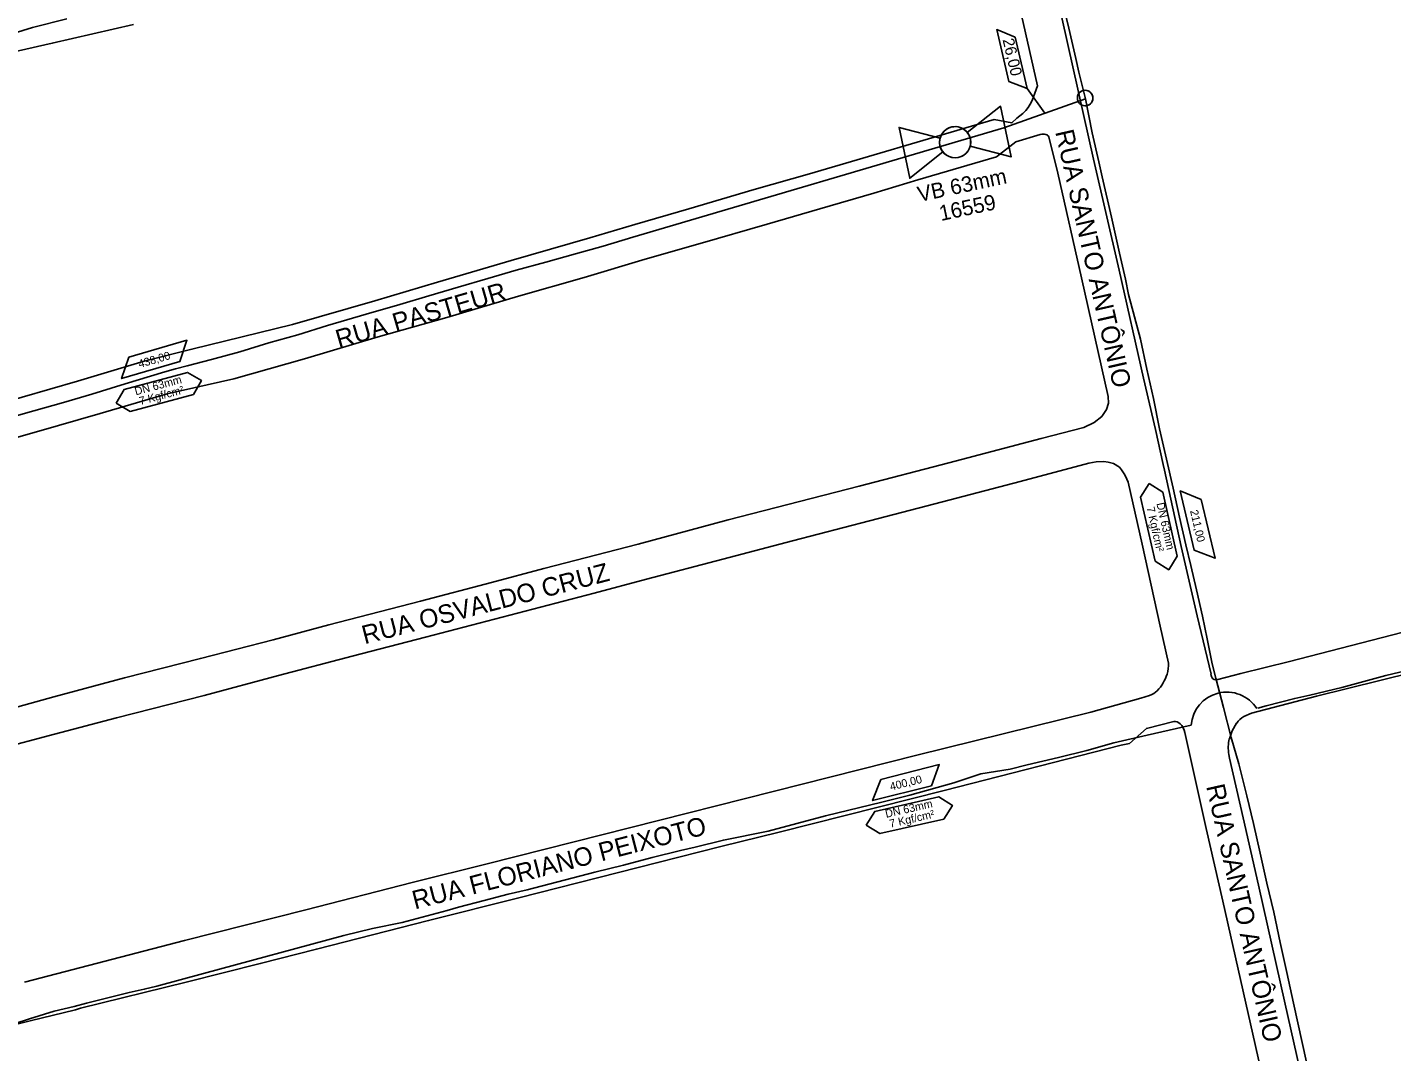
# Model space of a CAD drawing. Extents: x 656692 to 673945, y 7585994 to 7599066.
# Drawn here: x 669316 to 669847, y 7594394 to 7594792 of the extents above; entities that cross this region are included whole.
import ezdxf

# ---------------------------------------------------------------- set-up
doc = ezdxf.new("R2010")
doc.units = 0
for name, color, linetype in [('LEADER', 7, 'Continuous'), ('LOGRADOURO', 7, 'Continuous'), ('LOGRADOURO_TEXTO', 7, 'Continuous'), ('MEIO FIO', 7, 'Continuous'), ('SIMBOLO', 7, 'Continuous'), ('TEXTO', 7, 'Continuous'), ('TUBO_PEAD_GN_63', 7, 'Continuous'), ('VALVULA_PEAD_63', 7, 'Continuous')]:
    doc.layers.add(name, color=color, linetype=linetype)

# ---------------------------------------------------------------- blocks, each defined once
blk = doc.blocks.new('INTERLIGACAO_9')
at = {"layer": 'SIMBOLO'}
blk.add_circle((0, 0), 4.19, dxfattribs=at)
for start, end in [(0, 180), (180, 0)]:
    blk.add_arc((0, 0), 4.19, start, end, dxfattribs=at)
blk = doc.blocks.new('VALVULA_PEAD_DN_16')
at = {"layer": 'VALVULA_PEAD_63'}
for points in [[(-0.0374, 0.0187), (-0.1395, 0.0698), (-0.1395, -0.0698), (-0.0374, -0.0187)], [(-0.0374, -0.0187), (-0.1395, -0.0698), (-0.1395, 0.0698), (-0.0374, 0.0187)], [(0.0374, -0.0187), (0.1395, -0.0698), (0.1395, 0.0698), (0.0374, 0.0187)], [(0.0374, -0.0187), (0.1395, -0.0698), (0.1395, 0.0698), (0.0374, 0.0187)]]:
    blk.add_lwpolyline(points, dxfattribs=at)
blk.add_circle((0, 0), 0.0419, dxfattribs=at)
for start, end in [(90, 270), (270, 90), (153.4349, 206.5651), (333.4349, 26.5651)]:
    blk.add_arc((0, 0), 0.0419, start, end, dxfattribs=at)

msp = doc.modelspace()

# ---------------------------------------------------------------- linework, layer by layer
at = {"layer": 'LEADER'}
msp.add_line((669705.15, 7594768.25), (669711.96, 7594758.65), dxfattribs=at)
at = {"layer": 'LOGRADOURO'}
for points in [[(669708.04, 7594766.52), (669709.08, 7594769.39), (669698.21, 7594817.63)], [(669357.4, 7594793.19), (669325.77, 7594785.92), (669299.44, 7594779.98), (669291.66, 7594778.21), (669288.9, 7594777.62), (669281.2, 7594775.94), (669248.67, 7594768.12), (669226.84, 7594761.44), (669204.91, 7594756.34), (669201.88, 7594754.21), (669198.59, 7594751.08), (669196.54, 7594747.55), (669195.4, 7594743.11), (669195.58, 7594737.81), (669202.58, 7594710.45), (669204.55, 7594702.59), (669213.03, 7594669.59), (669218.51, 7594648.19), (669222.91, 7594633.24), (669224.67, 7594630.86), (669228.67, 7594628.02), (669233.37, 7594626.44), (669237.53, 7594626.34)], [(669237.1, 7594626.35), (669237.53, 7594626.34), (669243.7, 7594627.82), (669256.03, 7594631.66), (669281.62, 7594638.85), (669335.66, 7594654.49), (669361.52, 7594662.29), (669380.11, 7594666.85), (669419.27, 7594676.5), (669451.28, 7594685.7), (669475.65, 7594692.9), (669504.32, 7594701.36), (669535, 7594710.23), (669552.51, 7594715.34), (669573.47, 7594721.5), (669598.86, 7594729.05), (669620.42, 7594735.05), (669641.21, 7594741.19), (669692.23, 7594756.22), (669699.16, 7594754.93), (669701.07, 7594756.72)], [(669710.23, 7594750.4), (669700.67, 7594747.62), (669693.24, 7594741.71), (669662.53, 7594732.82), (669645.51, 7594727.58), (669624.46, 7594721.46), (669603.9, 7594715.53), (669577.86, 7594708.04), (669556.46, 7594701.88), (669532.76, 7594694.82), (669507.17, 7594687.54), (669479.33, 7594679.26), (669452.63, 7594671.71), (669423.99, 7594663.08), (669396.46, 7594655.38), (669370.52, 7594649.55), (669344.42, 7594641.91), (669319.65, 7594634.78), (669289.4, 7594626.23), (669263.46, 7594618.92)], [(669716.75, 7594736.58), (669717.02, 7594735.41), (669713.54, 7594749.5)], [(669717.02, 7594735.41), (669726.21, 7594694.71), (669736.62, 7594648.53), (669736.77, 7594645.94), (669736.02, 7594643.39), (669734.15, 7594640.73), (669731.23, 7594638.36), (669727.21, 7594636.49), (669710.61, 7594632.21), (669674.58, 7594622.69), (669639.78, 7594613.65), (669588.78, 7594600.48), (669553.81, 7594591.1), (669517.03, 7594581.51), (669496.65, 7594576.18), (669469.07, 7594568.91), (669433.42, 7594559.71), (669411.7, 7594553.81), (669383.46, 7594546.62), (669353.86, 7594539.03), (669326.39, 7594531.68), (669299.71, 7594524.3)], [(669789.44, 7594524.01), (669792.46, 7594525.26), (669817.72, 7594531.85), (669854.93, 7594541.17)], [(669317.17, 7594405.59), (669334.78, 7594409.84), (669336.84, 7594410.54), (669377.87, 7594420.65), (669406.73, 7594427.88), (669428.57, 7594433.54), (669472.21, 7594444.57), (669507.35, 7594453.49), (669561.45, 7594467.14), (669585.87, 7594473.39), (669608.65, 7594479.02), (669672.81, 7594495.25), (669741.75, 7594512.81), (669744.93, 7594513.55), (669751.5, 7594519.38), (669762.15, 7594522.05)], [(669766.41, 7594517.77), (669772.45, 7594490.95), (669774.82, 7594480.45), (669781.23, 7594452.2), (669791.14, 7594408.52), (669796.84, 7594383.21)], [(669783.78, 7594515.34), (669784.86, 7594518.45), (669786.63, 7594521.44)], [(670024.2, 7594248.68), (669972.2, 7594236.37), (669931.63, 7594226.92), (669869.93, 7594210.34), (669856.39, 7594207.15), (669854.57, 7594207.25), (669852.09, 7594209.19), (669851.15, 7594212.12), (669848.91, 7594221.72), (669841.45, 7594254.98), (669835.32, 7594280.76), (669830.05, 7594304.69), (669825.15, 7594326.15), (669817.99, 7594357.4), (669812.29, 7594382.1), (669805.54, 7594412.15), (669795.17, 7594458.34), (669789.2, 7594484.52), (669783.85, 7594507.78), (669783.6, 7594509.19)], [(669317.17, 7594405.59), (669298.03, 7594400.79), (669290.46, 7594398.86), (669287.17, 7594397.24), (669285.24, 7594393.34), (669285.69, 7594389.46), (669291.47, 7594367.59), (669298.18, 7594341.51), (669310.16, 7594295.23), (669315.1, 7594276.26), (669319.11, 7594267.04), (669323.78, 7594264.11), (669327.81, 7594262.48), (669331.42, 7594262.39), (669350.64, 7594266.44)]]:
    msp.add_lwpolyline(points, dxfattribs=at)
for centre, radius, start, end in [((669692.28, 7594770.35), 16.22, 302.7974, 346.333), ((669711.46, 7594745.18), 5.36, 79.6086, 103.2517), ((669711.99, 7594748.81), 1.7, 24.0037, 75.1752), ((669793.34, 7594516.94), 8.07, 118.8277, 146.1888), ((669762.33, 7594518.35), 3.71, 50.2693, 92.8497), ((669759.22, 7594516.32), 7.34, 11.4245, 41.6393), ((669798.13, 7594511.86), 14.77, 166.3521, 190.3999)]:
    msp.add_arc(centre, radius, start, end, dxfattribs=at)
at = {"layer": 'MEIO FIO'}
for p, q in [((669730.96, 7594740.8), (669716.35, 7594806.03)), ((669740.87, 7594697.65), (669730.96, 7594740.8)), ((669730.96, 7594740.8), (669730.96, 7594740.8)), ((669750.33, 7594655.62), (669740.87, 7594697.65)), ((669740.87, 7594697.65), (669740.87, 7594697.65)), ((669755.03, 7594635.61), (669750.33, 7594655.62)), ((669750.33, 7594655.62), (669750.33, 7594655.62)), ((669758.02, 7594622), (669755.03, 7594635.61)), ((669755.03, 7594635.61), (669755.03, 7594635.61)), ((669729.16, 7594622.59), (669702.34, 7594615.4)), ((669732.01, 7594623.08), (669729.16, 7594622.59)), ((669729.16, 7594622.59), (669729.16, 7594622.59)), ((669734.92, 7594623.14), (669732.01, 7594623.08)), ((669732.01, 7594623.08), (669732.01, 7594623.08)), ((669736.61, 7594622.99), (669734.92, 7594623.14)), ((669734.92, 7594623.14), (669734.92, 7594623.14)), ((669738.67, 7594622.45), (669736.61, 7594622.99)), ((669736.61, 7594622.99), (669736.61, 7594622.99)), ((669741.04, 7594620.94), (669738.67, 7594622.45)), ((669738.67, 7594622.45), (669738.67, 7594622.45)), ((669741.87, 7594619.94), (669741.04, 7594620.94)), ((669741.04, 7594620.94), (669741.04, 7594620.94)), ((669742.92, 7594618.4), (669741.87, 7594619.94)), ((669741.87, 7594619.94), (669741.87, 7594619.94)), ((669758.52, 7594619.77), (669758.02, 7594622)), ((669758.02, 7594622), (669758.02, 7594622)), ((669765.09, 7594590.11), (669758.52, 7594619.77)), ((669758.52, 7594619.77), (669758.52, 7594619.77)), ((669702.34, 7594615.4), (669672.24, 7594607.5)), ((669702.34, 7594615.4), (669702.34, 7594615.4)), ((669743.43, 7594617.51), (669742.92, 7594618.4)), ((669742.92, 7594618.4), (669742.92, 7594618.4)), ((669744.38, 7594615.11), (669743.43, 7594617.51)), ((669743.43, 7594617.51), (669743.43, 7594617.51)), ((669749.88, 7594591.01), (669744.38, 7594615.11)), ((669744.38, 7594615.11), (669744.38, 7594615.11)), ((669672.24, 7594607.5), (669643.71, 7594600.12)), ((669672.24, 7594607.5), (669672.24, 7594607.5)), ((669643.71, 7594600.12), (669613.86, 7594592.31)), ((669643.71, 7594600.12), (669643.71, 7594600.12)), ((669613.86, 7594592.31), (669586.69, 7594585.25)), ((669613.86, 7594592.31), (669613.86, 7594592.31)), ((669756.9, 7594559.18), (669749.88, 7594591.01)), ((669749.88, 7594591.01), (669749.88, 7594591.01)), ((669771.26, 7594563.21), (669765.09, 7594590.11)), ((669765.09, 7594590.11), (669765.09, 7594590.11)), ((669586.69, 7594585.25), (669556.98, 7594577.39)), ((669586.69, 7594585.25), (669586.69, 7594585.25)), ((669556.98, 7594577.39), (669536.6, 7594572.02)), ((669556.98, 7594577.39), (669556.98, 7594577.39)), ((669536.6, 7594572.02), (669500.8, 7594562.7)), ((669536.6, 7594572.02), (669536.6, 7594572.02)), ((669500.8, 7594562.7), (669471.07, 7594554.92)), ((669500.8, 7594562.7), (669500.8, 7594562.7)), ((669776.65, 7594540.51), (669771.26, 7594563.21)), ((669771.26, 7594563.21), (669771.26, 7594563.21)), ((669471.07, 7594554.92), (669442.49, 7594547.52)), ((669471.07, 7594554.92), (669471.07, 7594554.92)), ((669760.12, 7594544.79), (669756.9, 7594559.18)), ((669756.9, 7594559.18), (669756.9, 7594559.18)), ((669854.97, 7594557.66), (669807.25, 7594545.44)), ((669442.49, 7594547.52), (669413.86, 7594539.9)), ((669442.49, 7594547.52), (669442.49, 7594547.52)), ((669760.12, 7594544.79), (669760.12, 7594544.79)), ((669807.25, 7594545.44), (669788.25, 7594540.66)), ((669807.25, 7594545.44), (669807.25, 7594545.44)), ((669413.86, 7594539.9), (669384.92, 7594532.12)), ((669413.86, 7594539.9), (669413.86, 7594539.9)), ((669759.53, 7594540.49), (669759.53, 7594540.49)), ((669776.65, 7594540.51), (669776.65, 7594540.51)), ((669788.25, 7594540.66), (669779.34, 7594538.42)), ((669788.25, 7594540.66), (669788.25, 7594540.66)), ((669755.76, 7594534.01), (669755.76, 7594534.01)), ((669779.34, 7594538.42), (669779.34, 7594538.42)), ((669384.92, 7594532.12), (669350.83, 7594523.45)), ((669384.92, 7594532.12), (669384.92, 7594532.12)), ((669729.9, 7594525.7), (669749.34, 7594531.17)), ((669749.34, 7594531.17), (669752.78, 7594532.2)), ((669749.34, 7594531.17), (669749.34, 7594531.17)), ((669752.78, 7594532.2), (669752.78, 7594532.2)), ((669350.83, 7594523.45), (669326.62, 7594517.09)), ((669350.83, 7594523.45), (669350.83, 7594523.45)), ((669662.16, 7594508.99), (669729.9, 7594525.7)), ((669729.9, 7594525.7), (669729.9, 7594525.7)), ((669326.62, 7594517.09), (669299.28, 7594509.87)), ((669326.62, 7594517.09), (669326.62, 7594517.09)), ((669495.07, 7594466.67), (669662.16, 7594508.99)), ((669662.16, 7594508.99), (669662.16, 7594508.99)), ((669465.88, 7594459.48), (669495.07, 7594466.67)), ((669495.07, 7594466.67), (669495.07, 7594466.67)), ((669424.45, 7594448.75), (669465.88, 7594459.48)), ((669465.88, 7594459.48), (669465.88, 7594459.48)), ((669377.26, 7594436.84), (669424.45, 7594448.75)), ((669424.45, 7594448.75), (669424.45, 7594448.75)), ((669314.98, 7594420.66), (669377.26, 7594436.84)), ((669377.26, 7594436.84), (669377.26, 7594436.84))]:
    msp.add_line(p, q, dxfattribs=at)
for centre, radius, start, end in [((669745.85, 7594544.55), 14.27, 343.5106, 0.9964), ((669744.23, 7594545.06), 15.97, 316.2326, 343.4025), ((669778.63, 7594540.29), 2, 173.6588, 290.846), ((669748.73, 7594542.24), 10.82, 291.9604, 310.5304)]:
    msp.add_arc(centre, radius, start, end, dxfattribs=at)
at = {"layer": 'SIMBOLO'}
for points in [[(669350.63, 7594645.84), (669353.77, 7594651.26), (669378.44, 7594657.83), (669383.86, 7594654.7), (669380.72, 7594649.28), (669356.05, 7594642.71), (669350.63, 7594645.84)], [(669752.6, 7594614.65), (669757.9, 7594611.31), (669763.54, 7594586.41), (669760.21, 7594581.11), (669754.91, 7594584.45), (669749.27, 7594609.35), (669752.6, 7594614.65)], [(669642.5, 7594481.75), (669645.82, 7594487.05), (669670.71, 7594492.75), (669676.02, 7594489.42), (669672.69, 7594484.12), (669647.8, 7594478.42), (669642.5, 7594481.75)]]:
    msp.add_lwpolyline(points, dxfattribs=at)
at = {"layer": 'TEXTO'}
for points in [[(669700.44, 7594788.3), (669705.15, 7594768.25), (669697.99, 7594771.02), (669693.26, 7594791.2), (669700.44, 7594788.3)], [(669355.62, 7594663.83), (669378.2, 7594670.37), (669375.46, 7594662.04), (669352.74, 7594655.46), (669355.62, 7594663.83)], [(669772.86, 7594608.43), (669778.23, 7594585.55), (669770.06, 7594588.71), (669764.66, 7594611.74), (669772.86, 7594608.43)], [(669772.86, 7594608.43), (669778.23, 7594585.55), (669770.06, 7594588.71), (669764.66, 7594611.73), (669772.86, 7594608.43)], [(669648.12, 7594499.54), (669670.91, 7594505.28), (669667.88, 7594497.06), (669644.95, 7594491.29), (669648.12, 7594499.54)], [(669648.12, 7594499.54), (669670.91, 7594505.28), (669667.88, 7594497.06), (669644.95, 7594491.29), (669648.12, 7594499.54)]]:
    msp.add_lwpolyline(points, dxfattribs=at)
at = {"layer": 'TUBO_PEAD_GN_63'}
for points in [[(669196.25, 7594762.02), (669207.32, 7594764.89), (669217.32, 7594766.63), (669226.36, 7594768.54), (669242.04, 7594772.38), (669251.16, 7594774.72), (669262.75, 7594777.3), (669282.74, 7594782.15), (669287.91, 7594783.55), (669306.79, 7594788.48), (669318.14, 7594792.08), (669331.45, 7594795.44)], [(669720.07, 7594797.09), (669721.31, 7594791.75), (669724.02, 7594780.02), (669725.26, 7594774.64), (669727.87, 7594764.31), (669730.38, 7594751.05), (669733.04, 7594739.73), (669734.26, 7594733.94), (669737.97, 7594718.28), (669741.05, 7594704.21), (669743.37, 7594694.07), (669744.51, 7594688.13), (669749.23, 7594670.81), (669751.7, 7594659.1), (669754.23, 7594647.76), (669756.62, 7594635.96), (669759.39, 7594624.11), (669761.96, 7594612.88), (669764.42, 7594601.52), (669766.81, 7594590.78), (669768.83, 7594582.76), (669770.96, 7594573.22), (669773.36, 7594563), (669775.12, 7594554.16), (669777.15, 7594544.46), (669778.48, 7594538.86), (669781.49, 7594527.56), (669784.54, 7594515.77), (669787.47, 7594505.58), (669790.56, 7594493.16), (669793.2, 7594482.43), (669795.83, 7594470.78), (669798.39, 7594459.17), (669801.11, 7594447.83), (669803.62, 7594436.06), (669806.15, 7594424.35), (669808.76, 7594412.5), (669813.77, 7594389.54)], [(669307.21, 7594639.72), (669318.68, 7594642.93), (669330.13, 7594646.16), (669341.14, 7594649.45), (669352.48, 7594652.84), (669358.44, 7594654.7), (669369.53, 7594658.04), (669373.74, 7594659.22), (669378.28, 7594660.48), (669387.76, 7594662.93), (669398.83, 7594665.88), (669410.08, 7594669.36), (669421.35, 7594672.45), (669432.93, 7594676.09), (669447.89, 7594680.47), (669461.03, 7594684.22), (669472.3, 7594687.64), (669483.76, 7594691.01), (669495.31, 7594694.41), (669506.3, 7594697.69), (669517.89, 7594700.76), (669529.4, 7594704.01), (669540.13, 7594706.99), (669551.64, 7594710.53), (669696.05, 7594752.98), (669727.87, 7594764.31)], [(669794.93, 7594527.2), (669798.16, 7594528.16), (669809.2, 7594531.02), (669815.14, 7594532.26), (669827.58, 7594535.32), (669837.56, 7594538.01), (669844.61, 7594539.91), (669856.07, 7594542.64), (669867.56, 7594545.57), (669879.33, 7594548.46), (669890.47, 7594551.11), (669902.17, 7594553.92), (669913.53, 7594556.8), (669925.82, 7594560.46), (669943.06, 7594564.47), (669948.31, 7594565.8), (669956.63, 7594568.29), (669974.96, 7594572.99), (669990.06, 7594576.8), (670001.22, 7594579.53), (670013.49, 7594582.64), (670019.2, 7594584.4), (670025.24, 7594585.84), (670040.58, 7594590.73)], [(669305.32, 7594402.62), (669316.88, 7594406.43), (669326.58, 7594409.38), (669334.27, 7594411.14), (669339.12, 7594412.46), (669355.77, 7594416.57), (669361.61, 7594417.9), (669366.53, 7594419.11), (669384.69, 7594424.02), (669439.3, 7594438.77), (669450.4, 7594441.48), (669461.88, 7594443.8), (669479.49, 7594448.55), (669483.8, 7594449.84), (669493.85, 7594452.4), (669503.15, 7594454.87), (669510.54, 7594456.62), (669536.84, 7594463.47), (669548.11, 7594466.13), (669559.21, 7594469.1), (669570.29, 7594471.87), (669575.98, 7594473.22), (669586.96, 7594475.95), (669604.39, 7594479.38), (669626.65, 7594485.29), (669648.54, 7594490.61), (669659.47, 7594493.39), (669676.62, 7594498.18), (669687.03, 7594501.66), (669698.5, 7594503.5), (669705.06, 7594505.18), (669717.31, 7594508.09), (669728.28, 7594510.83), (669738.89, 7594513.75), (669751.76, 7594516.69), (669763.22, 7594519.32), (669768.95, 7594520.63)]]:
    msp.add_lwpolyline(points, dxfattribs=at)
msp.add_arc((669782.77, 7594519.64), 13.85, 32.3879, 175.9075, dxfattribs=at)

# ---------------------------------------------------------------- block references
at = {"layer": 'SIMBOLO', "xscale": 0.7229249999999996, "yscale": 0.7229249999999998, "rotation": 166.312122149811}
msp.add_blockref('INTERLIGACAO_9', (669727.67, 7594764.6), dxfattribs=at)
msp.add_blockref('INTERLIGACAO_9', (669727.67, 7594764.6), dxfattribs=at)
msp.add_blockref('INTERLIGACAO_9', (669727.67, 7594764.6), dxfattribs=at)
at = {"layer": 'VALVULA_PEAD_63', "xscale": 144.5849999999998, "yscale": 144.58499999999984, "rotation": 11.818565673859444}
msp.add_blockref('VALVULA_PEAD_DN_16', (669677.08, 7594747.41), dxfattribs=at)

# ---------------------------------------------------------------- texts
for s, p in [('VB 63mm', (669663.15, 7594724.13)), ('16559', (669671.58, 7594716.73))]:
    msp.add_text(s, height=6, rotation=12.048).set_placement(p)
at = {"layer": 'LOGRADOURO_TEXTO'}
for s, rotation, p in [('RUA SANTO ANTÔNIO', 282.7896, (669716, 7594751.48)), ('RUA PASTEUR', 16.1858, (669437.28, 7594667.15)), ('RUA OSVALDO CRUZ', 14.5413, (669447.32, 7594552.08)), ('RUA SANTO ANTÔNIO', 282.7896, (669774.72, 7594496.87)), ('RUA FLORIANO PEIXOTO', 14.4566, (669466.88, 7594448.92))]:
    msp.add_text(s, height=7.2, rotation=rotation, dxfattribs=at).set_placement(p)
at = {"layer": 'TEXTO'}
for s, height, rotation, p in [('26,00', 4.447, 283.1976, (669695.52, 7594787.29)), ('438,00', 3.113, 16.1556, (669359.77, 7594659.57)), ('DN 63mm', 3.113, 14.9251, (669358.31, 7594648.93)), ('7 Kgf/cm²', 3.113, 14.9251, (669360.07, 7594645.13)), ('7 Kgf/cm²', 3.113, 282.775, (669751.54, 7594605.24)), ('DN 63mm', 3.113, 282.775, (669755.4, 7594606.86)), ('211,00', 3.113, 283.1976, (669768.48, 7594604)), ('400,00', 3.113, 14.1279, (669652.11, 7594495.14)), ('DN 63mm', 3.113, 12.8974, (669650.28, 7594484.56)), ('7 Kgf/cm²', 3.113, 12.8974, (669651.91, 7594480.7))]:
    msp.add_text(s, height=height, rotation=rotation, dxfattribs=at).set_placement(p)

doc.saveas('drawing.dxf')
